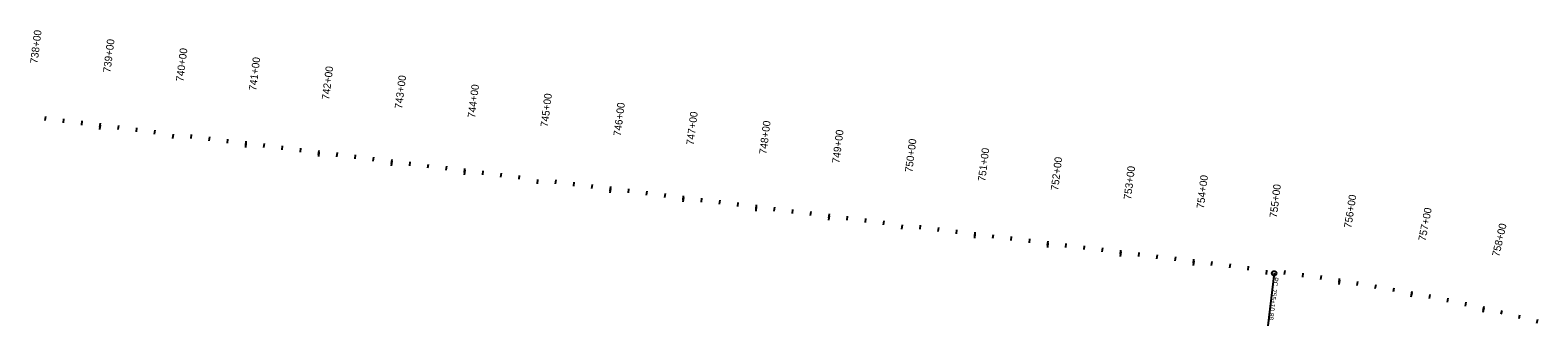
# Model space of a CAD drawing. Extents: x 19404354 to 19412652, y 7588762 to 7591481.
# Drawn here: x 19408512 to 19410565, y 7590540 to 7590943 of the extents above; entities that cross this region are included whole.
import ezdxf

# ---------------------------------------------------------------- set-up
doc = ezdxf.new("R2010")
doc.units = 0
for name, color, linetype in [('dsnNonPlotable', 7, 'Continuous'), ('dsnStdShading', 7, 'Continuous'), ('EdgeShoulder', 7, 'Continuous')]:
    doc.layers.add(name, color=color, linetype=linetype)

msp = doc.modelspace()

# ---------------------------------------------------------------- linework, layer by layer
at = {"layer": 'dsnNonPlotable'}
msp.add_line((19410205.9, 7590611.8), (19410197.1, 7590540.3), dxfattribs=at)
msp.add_circle((19410205.9, 7590611.8), 3.12, dxfattribs=at)
at = {"layer": 'dsnStdShading'}
for p, q in [((19408607.4, 7590810.6), (19408608, 7590816)), ((19408707, 7590801.3), (19408706.2, 7590795.2)), ((19408805.9, 7590786), (19408806.5, 7590791.4)), ((19408905.1, 7590773.6), (19408905.8, 7590779)), ((19409004.3, 7590761.3), (19409005, 7590766.7)), ((19409103.6, 7590748.9), (19409104.2, 7590754.4)), ((19409203.2, 7590739.6), (19409202.4, 7590733.6)), ((19409302, 7590724.2), (19409302.7, 7590729.7)), ((19409401.3, 7590711.9), (19409401.9, 7590717.3)), ((19409500.5, 7590699.5), (19409501.2, 7590705)), ((19409599.7, 7590687.2), (19409600.4, 7590692.6)), ((19409699.3, 7590677.9), (19409698.6, 7590671.8)), ((19409798.2, 7590662.5), (19409798.9, 7590667.9)), ((19409897.4, 7590650.2), (19409898.1, 7590655.6)), ((19409996.7, 7590637.8), (19409997.3, 7590643.2)), ((19410095.9, 7590625.5), (19410096.6, 7590630.9)), ((19410195.5, 7590616.2), (19410194.8, 7590610.1)), ((19410294.2, 7590599.4), (19410295, 7590604.8)), ((19410392.7, 7590582.3), (19410393.7, 7590587.6)), ((19410490.6, 7590561.7), (19410491.8, 7590567))]:
    msp.add_line(p, q, dxfattribs=at)
at = {"layer": 'EdgeShoulder'}
for p, q in [((19408532.9, 7590819.8), (19408533.6, 7590825.2)), ((19408557.8, 7590816.7), (19408558.4, 7590822.1)), ((19408582.6, 7590813.6), (19408583.2, 7590819.1)), ((19408607.8, 7590813.6), (19408607, 7590807.5)), ((19408632.2, 7590807.5), (19408632.9, 7590812.9)), ((19408657, 7590804.4), (19408657.7, 7590809.8)), ((19408681.8, 7590801.3), (19408682.5, 7590806.8)), ((19408707, 7590801.3), (19408706.2, 7590795.2)), ((19408731.4, 7590795.2), (19408732.1, 7590800.6)), ((19408756.2, 7590792.1), (19408756.9, 7590797.5)), ((19408781, 7590789), (19408781.7, 7590794.4)), ((19408806.2, 7590789), (19408805.5, 7590782.9)), ((19408830.7, 7590782.9), (19408831.3, 7590788.3)), ((19408855.5, 7590779.8), (19408856.1, 7590785.2)), ((19408880.3, 7590776.7), (19408881, 7590782.1)), ((19408905.5, 7590776.7), (19408904.7, 7590770.6)), ((19408929.9, 7590770.5), (19408930.6, 7590776)), ((19408954.7, 7590767.5), (19408955.4, 7590772.9)), ((19408979.5, 7590764.4), (19408980.2, 7590769.8)), ((19409004.7, 7590764.3), (19409003.9, 7590758.2)), ((19409029.1, 7590758.2), (19409029.8, 7590763.6)), ((19409053.9, 7590755.1), (19409054.6, 7590760.5)), ((19409078.8, 7590752), (19409079.4, 7590757.4)), ((19409103.9, 7590752), (19409103.2, 7590745.9)), ((19409128.4, 7590745.8), (19409129, 7590751.3)), ((19409153.2, 7590742.8), (19409153.9, 7590748.2)), ((19409178, 7590739.7), (19409178.7, 7590745.1)), ((19409203.2, 7590739.6), (19409202.4, 7590733.6)), ((19409227.6, 7590733.5), (19409228.3, 7590738.9)), ((19409252.4, 7590730.4), (19409253.1, 7590735.8)), ((19409277.2, 7590727.3), (19409277.9, 7590732.7)), ((19409302.4, 7590727.3), (19409301.7, 7590721.2)), ((19409326.8, 7590721.2), (19409327.5, 7590726.6)), ((19409351.6, 7590718.1), (19409352.3, 7590723.5)), ((19409376.5, 7590715), (19409377.1, 7590720.4)), ((19409401.6, 7590714.9), (19409400.9, 7590708.9)), ((19409426.1, 7590708.8), (19409426.7, 7590714.2)), ((19409450.9, 7590705.7), (19409451.6, 7590711.1)), ((19409475.7, 7590702.6), (19409476.4, 7590708.1)), ((19409500.9, 7590702.6), (19409500.1, 7590696.5)), ((19409525.3, 7590696.5), (19409526, 7590701.9)), ((19409550.1, 7590693.4), (19409550.8, 7590698.8)), ((19409574.9, 7590690.3), (19409575.6, 7590695.7)), ((19409600.1, 7590690.2), (19409599.4, 7590684.2)), ((19409624.5, 7590684.1), (19409625.2, 7590689.5)), ((19409649.4, 7590681), (19409650, 7590686.4)), ((19409674.2, 7590677.9), (19409674.8, 7590683.4)), ((19409699.3, 7590677.9), (19409698.6, 7590671.8)), ((19409723.8, 7590671.8), (19409724.5, 7590677.2)), ((19409748.6, 7590668.7), (19409749.3, 7590674.1)), ((19409773.4, 7590665.6), (19409774.1, 7590671)), ((19409798.6, 7590665.5), (19409797.8, 7590659.5)), ((19409823, 7590659.4), (19409823.7, 7590664.8)), ((19409847.8, 7590656.3), (19409848.5, 7590661.8)), ((19409872.6, 7590653.3), (19409873.3, 7590658.7)), ((19409897.8, 7590653.2), (19409897.1, 7590647.1)), ((19409922.2, 7590647.1), (19409922.9, 7590652.5)), ((19409947.1, 7590644), (19409947.7, 7590649.4)), ((19409971.9, 7590640.9), (19409972.5, 7590646.3)), ((19409997.1, 7590640.9), (19409996.3, 7590634.8)), ((19410021.5, 7590634.7), (19410022.2, 7590640.2)), ((19410046.3, 7590631.6), (19410047, 7590637.1)), ((19410071.1, 7590628.6), (19410071.8, 7590634)), ((19410096.3, 7590628.5), (19410095.5, 7590622.4)), ((19410120.7, 7590622.4), (19410121.4, 7590627.8)), ((19410145.5, 7590619.3), (19410146.2, 7590624.7)), ((19410170.3, 7590616.2), (19410171, 7590621.6)), ((19410195.5, 7590616.2), (19410194.8, 7590610.1)), ((19410219.9, 7590610), (19410220.7, 7590615.4)), ((19410244.7, 7590606.7), (19410245.5, 7590612.1)), ((19410269.5, 7590603.2), (19410270.3, 7590608.6)), ((19410294.7, 7590602.4), (19410293.7, 7590596.4)), ((19410318.9, 7590595.4), (19410319.8, 7590600.8)), ((19410343.5, 7590591.3), (19410344.5, 7590596.6)), ((19410368.1, 7590586.9), (19410369.1, 7590592.2)), ((19410393.3, 7590585.3), (19410392.1, 7590579.3)), ((19410417.2, 7590577.4), (19410418.3, 7590582.8)), ((19410441.7, 7590572.4), (19410442.9, 7590577.8)), ((19410466.2, 7590567.2), (19410467.3, 7590572.5)), ((19410491.2, 7590564.7), (19410489.9, 7590558.7)), ((19410514.9, 7590556), (19410516.2, 7590561.3)), ((19410539.2, 7590550.1), (19410540.5, 7590555.5)), ((19410563.5, 7590544.1), (19410564.8, 7590549.3))]:
    msp.add_line(p, q, dxfattribs=at)

# ---------------------------------------------------------------- texts
at = {"layer": 'dsnNonPlotable'}
for s, p in [('PC', (19410205.4, 7590606.9)), ('755+10.88', (19410203.4, 7590590.7))]:
    msp.add_text(s, height=6.48, rotation=262.9082, dxfattribs=at).set_placement(p)
at = {"layer": 'dsnStdShading'}
for s, rotation, p in [('740+00', 82.9303, (19408720.9, 7590872.1)), ('745+00', 82.9082, (19409217.1, 7590810.4)), ('750+00', 82.9082, (19409713.3, 7590748.7)), ('755+00', 82.9082, (19410209.5, 7590686.9))]:
    msp.add_text(s, height=10.2, rotation=rotation, dxfattribs=at).set_placement(p)
at = {"layer": 'EdgeShoulder'}
for s, rotation, p in [('738+00', 82.9303, (19408522.4, 7590896.7)), ('739+00', 82.9303, (19408621.7, 7590884.4)), ('740+00', 82.9303, (19408720.9, 7590872.1)), ('741+00', 82.9303, (19408820.1, 7590859.8)), ('742+00', 82.9082, (19408919.4, 7590847.4)), ('743+00', 82.9082, (19409018.6, 7590835.1)), ('744+00', 82.9082, (19409117.9, 7590822.7)), ('745+00', 82.9082, (19409217.1, 7590810.4)), ('746+00', 82.9082, (19409316.4, 7590798)), ('747+00', 82.9082, (19409415.6, 7590785.7)), ('748+00', 82.9082, (19409514.8, 7590773.3)), ('749+00', 82.9082, (19409614.1, 7590761)), ('750+00', 82.9082, (19409713.3, 7590748.7)), ('751+00', 82.9082, (19409812.5, 7590736.3)), ('752+00', 82.9082, (19409911.8, 7590724)), ('753+00', 82.9082, (19410011, 7590711.6)), ('754+00', 82.9082, (19410110.2, 7590699.3)), ('755+00', 82.9082, (19410209.5, 7590686.9)), ('756+00', 81.1284, (19410310.8, 7590672.7)), ('757+00', 79.1314, (19410411.9, 7590655)), ('758+00', 77.1344, (19410512.2, 7590633.7))]:
    msp.add_text(s, height=10.2, rotation=rotation, dxfattribs=at).set_placement(p)

doc.saveas('drawing.dxf')
